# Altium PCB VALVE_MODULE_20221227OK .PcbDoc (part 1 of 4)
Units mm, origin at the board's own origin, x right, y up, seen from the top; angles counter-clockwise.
Board outline 260.15 x 142.01 mm, 2 copper layers (Top Layer, Bottom Layer); 455 components, 212 nets, 1302 pads, 385 vias.
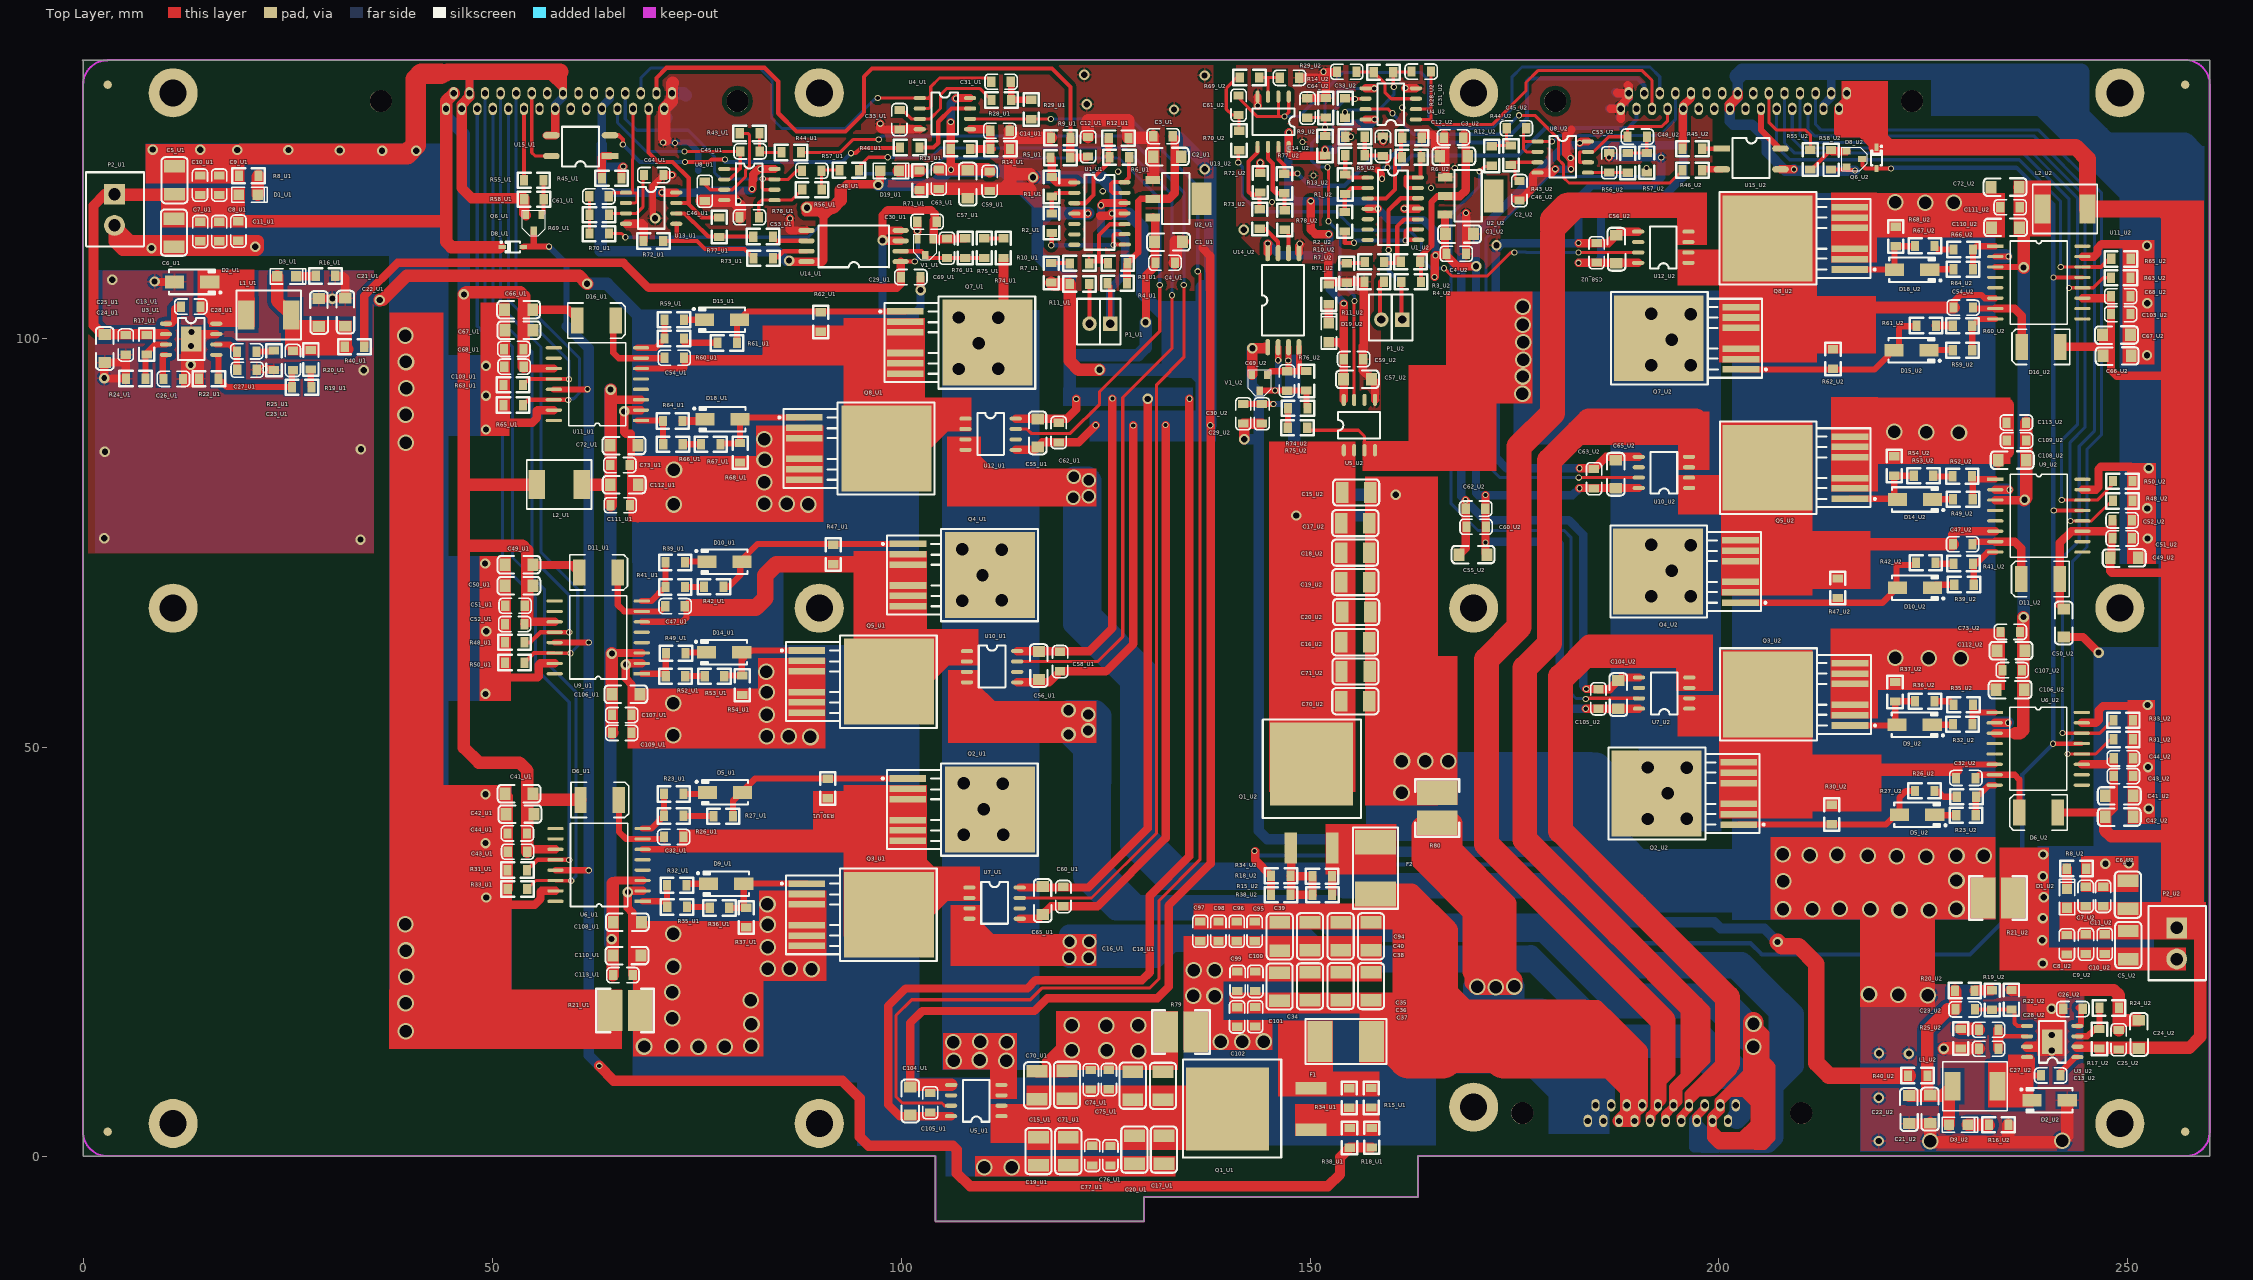
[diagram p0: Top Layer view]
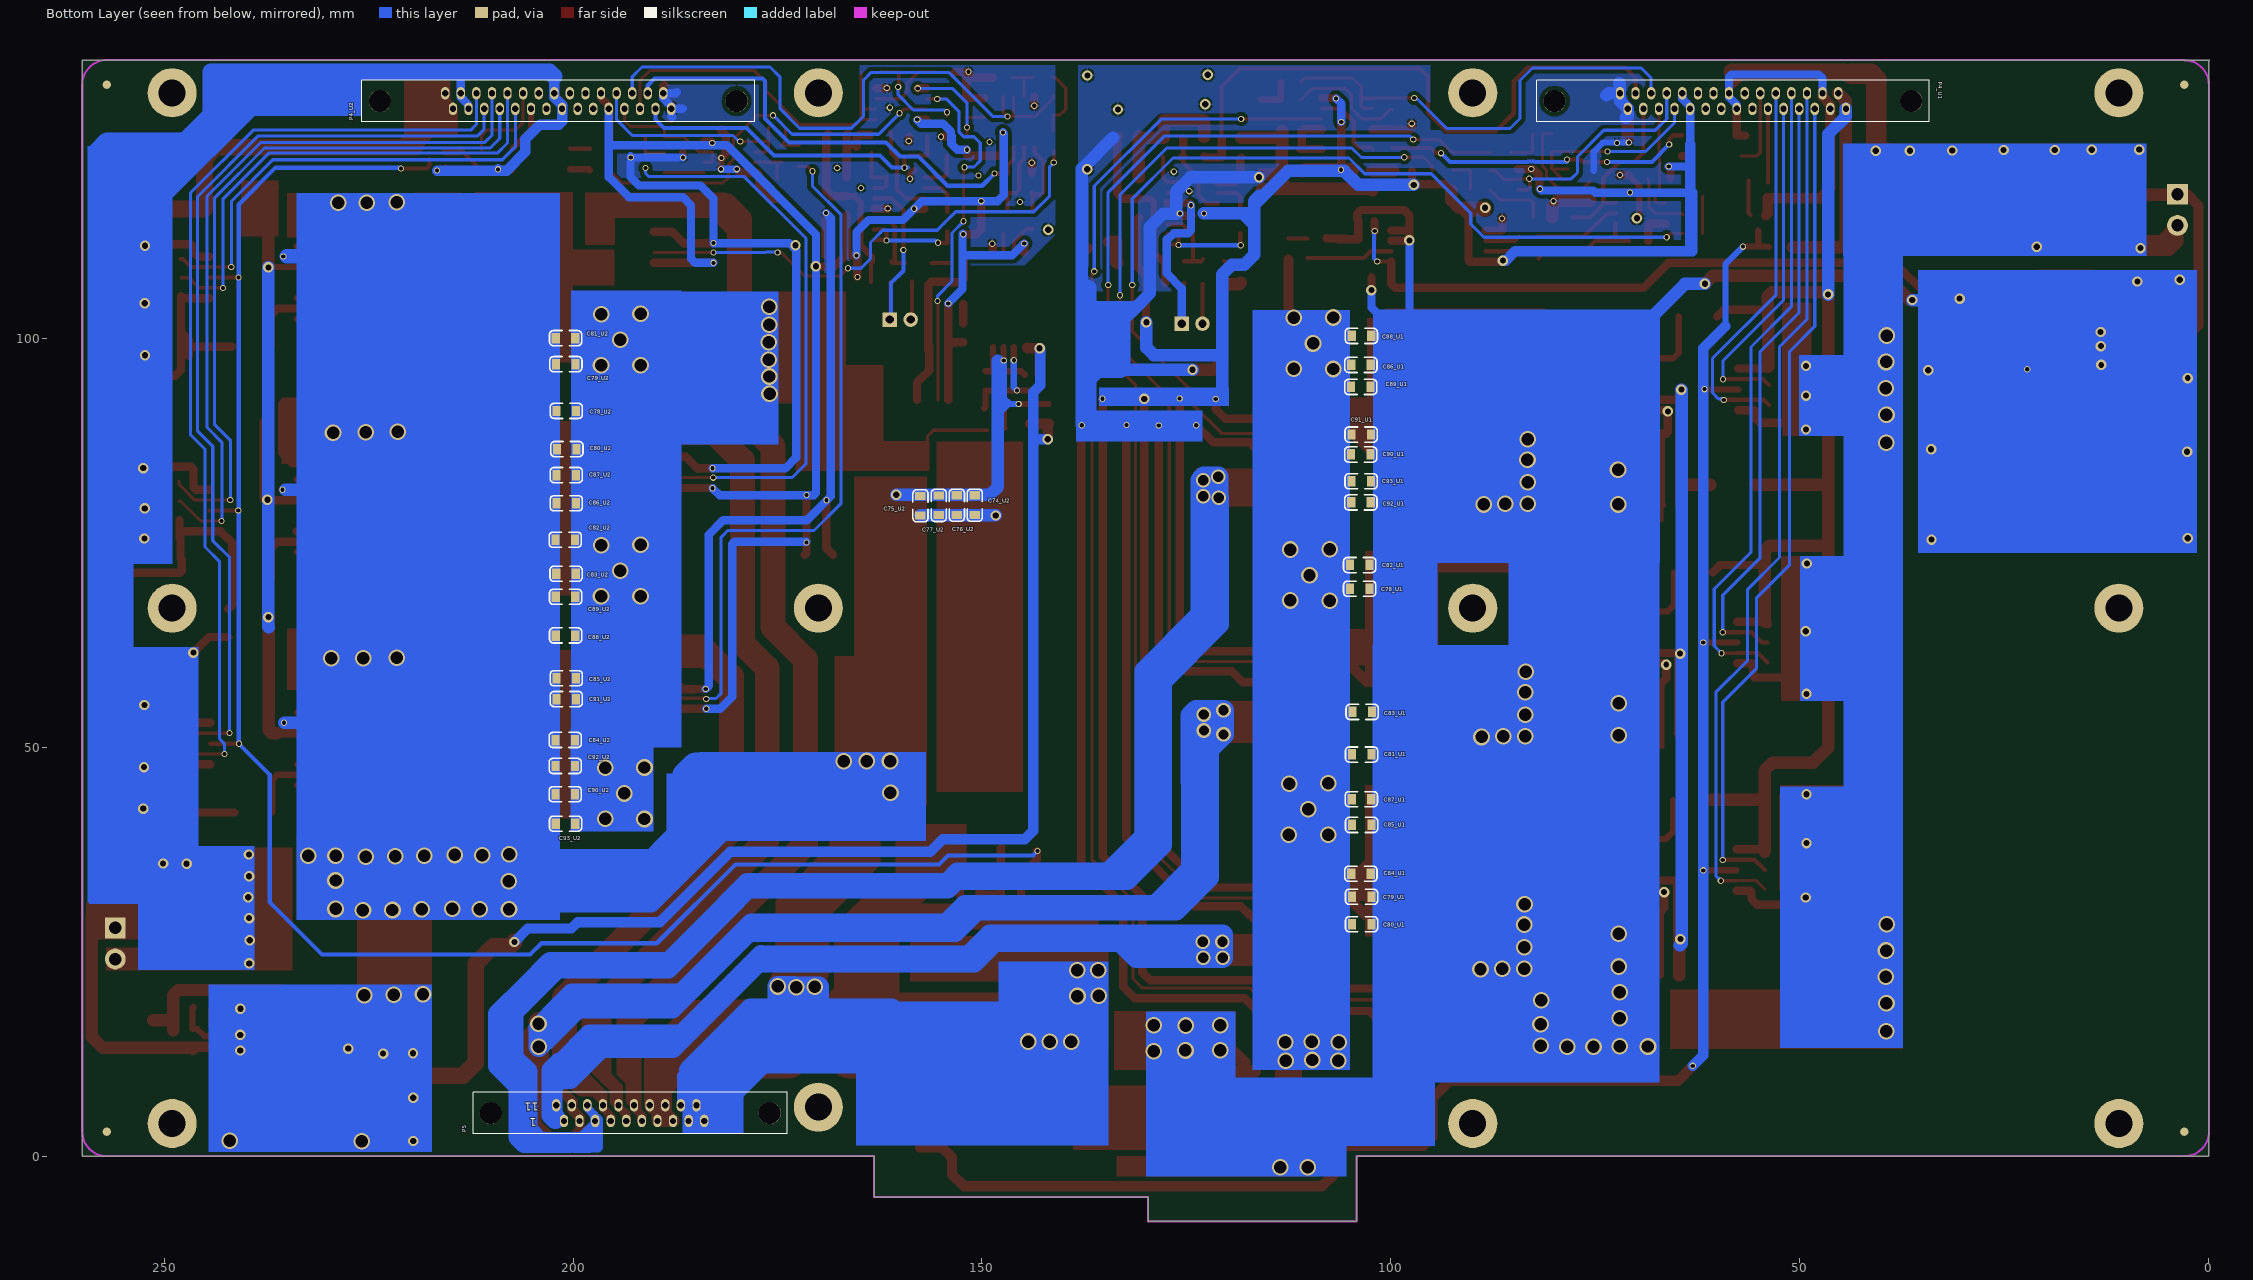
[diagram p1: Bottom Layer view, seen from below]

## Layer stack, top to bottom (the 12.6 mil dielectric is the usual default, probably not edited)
Top Layer: signal copper 0.0356
Dielectric: core 0.32, FR-4, Dk 4.8
Bottom Layer: signal copper 0.0356

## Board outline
-0.025,134.01 0,133.985 0,0 104.2,0 104.2,-7.925 129.624,-7.925 129.7,-8.001 129.7,-5 163.2,-5 163.2,0 260.02,0 260.02,134.01 -0.127,134.01

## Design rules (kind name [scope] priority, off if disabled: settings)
Clearance Clearance_1 [InPolygon] p1: gap=0.508
Clearance [All] p2: gap=0.254
HoleSize [All] p1: absolutevalues=TRUE maxlimit=12.7 minlimit=0.025 maxpercent=80.000 minpercent=20.000
MinimumSolderMaskSliver [All] p1: minsoldermaskwidth=0
PolygonConnect [All] p1: connectstyle=Relief reliefconductorwidth=0.254 reliefentries=4 polygonreliefangle="90 Angle" airgapwidth=0.254
RoutingVias [All] p1: holewidth=0.711 width=1.27 viastyle="Through Hole" minholewidth=0.508 minwidth=0.762 maxholewidth=2.032 maxwidth=2.54
SilkToSilkClearance [All] p1: silktosilkclearance=0
SilkToSolderMaskClearance [IsPad] p1: minsilkscreentomaskgap=0 clearancetoexposedcopper=TRUE
SolderMaskExpansion [All] p1: expansion=0.102
Width [All] p1: maxlimit=5.08 minlimit=0.254 preferedwidth=0.254 minimp=50.000000 maximp=50.000000 favimp=50.000000
24 further rules are at their usual default settings.

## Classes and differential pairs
channel class THREE_PHASE_MODULE: U1 U2
component class U3: C34 C35 C36 C37 C38 C39 C40 C94 C95 C96 C97 C98 C99 C100 C101 C102 F1 F2 P5 R79 R80
component class U2: C1_U2 C2_U2 C3_U2 C4_U2 C5_U2 C6_U2 C7_U2 C8_U2 C9_U2 C10_U2 C11_U2 C12_U2 C13_U2 C14_U2 C15_U2 C16_U2 C17_U2 C18_U2 C19_U2 C20_U2 C21_U2 C22_U2 C23_U2 C24_U2 C25_U2 C26_U2 C27_U2 C28_U2 C29_U2 C30_U2 C31_U2 C32_U2 C33_U2 C41_U2 C42_U2 C43_U2 C44_U2 C45_U2 C46_U2 C47_U2 C48_U2 C49_U2 C50_U2 C51_U2 C52_U2 C53_U2 C54_U2 C55_U2 C56_U2 C57_U2 C58_U2 C59_U2 C60_U2 C61_U2 C62_U2 C63_U2 C64_U2 C65_U2 C66_U2 C67_U2 C68_U2 C69_U2 C70_U2 C71_U2 C72_U2 C73_U2 C74_U2 C75_U2 C76_U2 C77_U2 C78_U2 C79_U2 C80_U2 C81_U2 C82_U2 C83_U2 C84_U2 C85_U2 C86_U2 C87_U2 C88_U2 C89_U2 C90_U2 C91_U2 C92_U2 C93_U2 C103_U2 C104_U2 C105_U2 C106_U2 C107_U2 C108_U2 C109_U2 C110_U2 C111_U2 C112_U2 C113_U2 D1_U2 D2_U2 D3_U2 D5_U2 D6_U2 D8_U2 D9_U2 D10_U2 D11_U2 D14_U2 D15_U2 D16_U2 D18_U2 D19_U2 L1_U2 L2_U2 P1_U2 P2_U2 P4_U2 Q1_U2 Q2_U2 Q3_U2 Q4_U2 Q5_U2 Q6_U2 Q7_U2 Q8_U2 R1_U2 R2_U2 R3_U2 R4_U2 R5_U2 R6_U2 R7_U2 R8_U2 R9_U2 R10_U2 R11_U2 R12_U2 R13_U2 R14_U2 R15_U2 R16_U2 R17_U2 R18_U2 R19_U2 R20_U2 R21_U2 R22_U2 R23_U2 R24_U2 R25_U2 R26_U2 R27_U2 R28_U2 R29_U2 R30_U2 R31_U2 R32_U2 R33_U2 R34_U2 R35_U2 R36_U2 R37_U2 R38_U2 R39_U2 R40_U2 R41_U2 R42_U2 R43_U2 R44_U2 R45_U2 R46_U2 R47_U2 R48_U2 R49_U2 R50_U2 R52_U2 R53_U2 R54_U2 R55_U2 R56_U2 R57_U2 R58_U2 R59_U2 R60_U2 R61_U2 R62_U2 R63_U2 R64_U2 R65_U2 R66_U2 R67_U2 R68_U2 R69_U2 R70_U2 R71_U2 R72_U2 R73_U2 R74_U2 R75_U2 R76_U2 R77_U2 R78_U2 U1_U2 U2_U2 U3_U2 U4_U2 U5_U2 U6_U2 U7_U2 U8_U2 U9_U2 U10_U2 U11_U2 U12_U2 U13_U2 U14_U2 U15_U2 V1_U2
component class U1: C1_U1 C2_U1 C3_U1 C4_U1 C5_U1 C6_U1 C7_U1 C8_U1 C9_U1 C10_U1 C11_U1 C12_U1 C13_U1 C14_U1 C15_U1 C16_U1 C17_U1 C18_U1 C19_U1 C20_U1 C21_U1 C22_U1 C23_U1 C24_U1 C25_U1 C26_U1 C27_U1 C28_U1 C29_U1 C30_U1 C31_U1 C32_U1 C33_U1 C41_U1 C42_U1 C43_U1 C44_U1 C45_U1 C46_U1 C47_U1 C48_U1 C49_U1 C50_U1 C51_U1 C52_U1 C53_U1 C54_U1 C55_U1 C56_U1 C57_U1 C58_U1 C59_U1 C60_U1 C61_U1 C62_U1 C63_U1 C64_U1 C65_U1 C66_U1 C67_U1 C68_U1 C69_U1 C70_U1 C71_U1 C72_U1 C73_U1 C74_U1 C75_U1 C76_U1 C77_U1 C78_U1 C79_U1 C80_U1 C81_U1 C82_U1 C83_U1 C84_U1 C85_U1 C86_U1 C87_U1 C88_U1 C89_U1 C90_U1 C91_U1 C92_U1 C93_U1 C103_U1 C104_U1 C105_U1 C106_U1 C107_U1 C108_U1 C109_U1 C110_U1 C111_U1 C112_U1 C113_U1 D1_U1 D2_U1 D3_U1 D5_U1 D6_U1 D8_U1 D9_U1 D10_U1 D11_U1 D14_U1 D15_U1 D16_U1 D18_U1 D19_U1 L1_U1 L2_U1 P1_U1 P2_U1 P4_U1 Q1_U1 Q2_U1 Q3_U1 Q4_U1 Q5_U1 Q6_U1 Q7_U1 Q8_U1 R1_U1 R2_U1 R3_U1 R4_U1 R5_U1 R6_U1 R7_U1 R8_U1 R9_U1 R10_U1 R11_U1 R12_U1 R13_U1 R14_U1 R15_U1 R16_U1 R17_U1 R18_U1 R19_U1 R20_U1 R21_U1 R22_U1 R23_U1 R24_U1 R25_U1 R26_U1 R27_U1 R28_U1 R29_U1 R30_U1 R31_U1 R32_U1 R33_U1 R34_U1 R35_U1 R36_U1 R37_U1 R38_U1 R39_U1 R40_U1 R41_U1 R42_U1 R43_U1 R44_U1 R45_U1 R46_U1 R47_U1 R48_U1 R49_U1 R50_U1 R52_U1 R53_U1 R54_U1 R55_U1 R56_U1 R57_U1 R58_U1 R59_U1 R60_U1 R61_U1 R62_U1 R63_U1 R64_U1 R65_U1 R66_U1 R67_U1 R68_U1 R69_U1 R70_U1 R71_U1 R72_U1 R73_U1 R74_U1 R75_U1 R76_U1 R77_U1 R78_U1 U1_U1 U2_U1 U3_U1 U4_U1 U5_U1 U6_U1 U7_U1 U8_U1 U9_U1 U10_U1 U11_U1 U12_U1 U13_U1 U14_U1 U15_U1 V1_U1

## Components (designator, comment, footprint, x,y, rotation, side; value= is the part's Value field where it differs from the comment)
C1_U1 "22uF/25V" WP_1206CC 130.988,111.785 r0 top (schematic designator C1)
C1_U2 "22uF/25V" WP_1206CC 166.573,112.751 r0 top (schematic designator C1)
C2_U1 "22uF/25V" WP_1206CC 134.264,122.199 r180 top (schematic designator C2)
C2_U2 "22uF/25V" WP_1206CC 169.291,122.225 r180 top (schematic designator C2)
C3_U1 "0.1uF/50V" WP_0805C 133.248,124.663 r180 top (schematic designator C3)
C3_U2 "0.1uF/50V" WP_0805C 168.758,124.511 r180 top (schematic designator C3)
C4_U1 "0.1uF/50V" WP_0805C 131.064,109.271 r0 top (schematic designator C4)
C4_U2 "0.1uF/50V" WP_0805C 166.675,110.363 r0 top (schematic designator C4)
C5_U1 "47uF/50V" WP_1210CC 11.176,117.602 r90 top (schematic designator C5)
C5_U2 "47uF/50V" WP_1210CC 250.038,27.534 r270 top (schematic designator C5)
C6_U1 "47uF/50V" WP_1210CC 11.1,114.63 r270 top (schematic designator C6)
C6_U2 "47uF/50V" WP_1210CC 249.987,30.251 r90 top (schematic designator C6)
C7_U1 "0.1uF/50V" WP_0805C 14.275,111.836 r90 top (schematic designator C7)
C7_U2 "0.1uF/50V" WP_0805C 244.856,32.969 r270 top (schematic designator C7)
C8_U1 "0.1uF/50V" WP_0805C 16.612,111.836 r90 top (schematic designator C8)
C8_U2 "0.1uF/50V" WP_0805C 242.494,24.638 r90 top (schematic designator C8)
C9_U1 "0.1uF/50V" WP_0805C 16.688,119.939 r270 top (schematic designator C9)
C9_U2 "0.1uF/50V" WP_0805C 244.831,24.714 r90 top (schematic designator C9)
C10_U1 "0.1uF/50V" WP_0805C 14.326,119.939 r270 top (schematic designator C10)
C10_U2 "0.1uF/50V" WP_0805C 247.117,24.714 r90 top (schematic designator C10)
C11_U1 "0.1uF/50V" WP_0805C 18.948,111.887 r90 top (schematic designator C11)
C11_U2 "0.1uF/50V" WP_0805C 246.99,32.969 r270 top (schematic designator C11)
C12_U1 "0.1uF/50V" WP_0805C 122.834,122.199 r90 top (schematic designator C12)
C12_U2 "0.1uF/50V" WP_0805C 158.877,122.25 r90 top (schematic designator C12)
C13_U1 "0.1uF/50V" WP_0805C 14.376,103.835 r180 top (schematic designator C13)
C13_U2 "0.1uF/50V" WP_0805C 239.344,9.906 r0 top (schematic designator C13)
C14_U1 "0.1uF/50V" WP_0805C 110.871,125.4 r0 top (schematic designator C14)
C14_U2 "0.1uF/50V" WP_0805C 149.657,126.924 r90 top (schematic designator C14)
C15_U1 "47uF/100V" WP_1210CC 120.294,7.01 r90 top (schematic designator C15)
C15_U2 "47uF/100V" WP_1210CC 153.924,81.153 r0 top (schematic designator C15)
C16_U1 "47uF/100V" WP_1210CC 128.321,6.909 r90 top (schematic designator C16)
C16_U2 "47uF/100V" WP_1210CC 153.797,62.84 r0 top (schematic designator C16)
C17_U1 "47uF/100V" WP_1210CC 132.131,2.515 r270 top (schematic designator C17)
C17_U2 "47uF/100V" WP_1210CC 153.822,77.394 r0 top (schematic designator C17)
C18_U1 "47uF/100V" WP_1210CC 132.029,6.883 r90 top (schematic designator C18)
C18_U2 "47uF/100V" WP_1210CC 153.797,73.787 r0 top (schematic designator C18)
C19_U1 "47uF/100V" WP_1210CC 116.789,2.337 r270 top (schematic designator C19)
C19_U2 "47uF/100V" WP_1210CC 153.822,70.18 r0 top (schematic designator C19)
C20_U1 "47uF/100V" WP_1210CC 128.524,2.515 r270 top (schematic designator C20)
C20_U2 "47uF/100V" WP_1210CC 153.924,66.523 r0 top (schematic designator C20)
C21_U1 "22uF/25V" WP_1206CC 28.829,101.422 r90 top (schematic designator C21)
C21_U2 "22uF/25V" WP_1206CC 225.806,7.468 r270 top (schematic designator C21)
C22_U1 "22uF/25V" WP_1206CC 32.055,101.473 r90 top (schematic designator C22)
C22_U2 "22uF/25V" WP_1206CC 223.241,7.417 r270 top (schematic designator C22)
C23_U1 "100pF/50V" WP_0805C 25.679,98.501 r270 top (schematic designator C23)
C23_U2 "100pF/50V" WP_0805C 228.879,17.983 r0 top (schematic designator C23)
C24_U1 "22uF/25V" WP_1206CC 2.667,100.457 r270 top (schematic designator C24)
C24_U2 "22uF/25V" WP_1206CC 251.333,13.183 r90 top (schematic designator C24)
C25_U1 "0.1uF/50V" WP_0805C 5.182,97.968 r90 top (schematic designator C25)
C25_U2 "0.1uF/50V" WP_0805C 248.895,15.443 r270 top (schematic designator C25)
C26_U1 "0.01uF/50V" WP_0805C 12.243,94.996 r180 top (schematic designator C26)
C26_U2 "0.01uF/50V" WP_0805C 242.062,18.034 r0 top (schematic designator C26)
C27_U1 "22pF/50V" WP_0805C 21.26,96.114 r180 top (schematic designator C27)
C27_U2 "22pF/50V" WP_0805C 231.75,13.183 r0 top (schematic designator C27)
C28_U1 "2.2nF/50V" WP_0805C 21.209,98.349 r180 top (schematic designator C28)
C28_U2 "2.2nF/50V" WP_0805C 231.75,15.494 r0 top (schematic designator C28)
C29_U1 "0.1uF/50V" WP_0805C 102.413,107.442 r180 top (schematic designator C29)
C29_U2 "0.1uF/50V" WP_0805C 144.145,91.973 r270 top (schematic designator C29)
C30_U1 "0.1uF/50V" WP_0805C 104.394,114.198 r180 top (schematic designator C30)
C30_U2 "0.1uF/50V" WP_0805C 141.884,91.973 r270 top (schematic designator C30)
C31_U1 "10nF/50V" WP_0805C 113.436,131.318 r180 top (schematic designator C31)
C31_U2 "10nF/50V" WP_0805C 162.382,132.639 r0 top (schematic designator C31)
C32_U1 "1uF/50V" WP_0805C 70.993,39.065 r0 top (schematic designator C32)
C32_U2 "1uF/50V" WP_0805C 231.394,46.203 r180 top (schematic designator C32)
C33_U1 "3.3nF/50V" WP_0805C 99.847,127.94 r270 top (schematic designator C33)
C33_U2 "3.3nF/50V" WP_0805C 155.702,132.537 r180 top (schematic designator C33)
C34 "47uF/100V" WP_1210CC 146.279,19.025 r90 top
C35 "47uF/100V" WP_1210CC 149.987,19.05 r90 top
C36 "47uF/100V" WP_1210CC 157.455,19.075 r90 top
C37 "47uF/100V" WP_1210CC 153.746,19.075 r90 top
C38 "47uF/100V" WP_1210CC 149.987,28.6 r270 top
C39 "47uF/100V" WP_1210CC 146.304,28.575 r270 top
C40 "47uF/100V" WP_1210CC 153.746,28.6 r270 top
C41_U1 "10uF/50V" WP_1206CC 55.016,44.298 r180 top (schematic designator C41)
C41_U2 "10uF/50V" WP_1206CC 247.218,44.069 r0 top (schematic designator C41)
C42_U1 "10uF/50V" WP_1206CC 55.118,41.808 r180 top (schematic designator C42)
C42_U2 "10uF/50V" WP_1206CC 247.218,41.478 r0 top (schematic designator C42)
C43_U1 "0.1uF/50V" WP_0805C 54.331,37.186 r180 top (schematic designator C43)
C43_U2 "0.1uF/50V" WP_0805C 248.234,46.507 r0 top (schematic designator C43)
C44_U1 "0.1uF/50V" WP_0805C 54.305,39.421 r180 top (schematic designator C44)
C44_U2 "0.1uF/50V" WP_0805C 248.234,48.666 r0 top (schematic designator C44)
C45_U1 "10nF/50V" WP_0805C 82.753,122.809 r180 top (schematic designator C45)
C45_U2 "10nF/50V" WP_0805C 174.015,125.705 r0 top (schematic designator C45)
C46_U1 "3.3nF/50V" WP_0805C 76.048,119.177 r270 top (schematic designator C46)
C46_U2 "3.3nF/50V" WP_0805C 175.641,119.253 r270 top (schematic designator C46)
C47_U1 "Cap Semi" WP_0805C 73.584,67.208 r180 top (schematic designator C47)
C47_U2 "Cap Semi" WP_0805C 228.575,74.854 r0 top (schematic designator C47)
C48_U1 "10nF/50V" WP_0805C 90.297,120.447 r180 top (schematic designator C48)
C48_U2 "10nF/50V" WP_0805C 191.237,124.612 r180 top (schematic designator C48)
C49_U1 "10uF/50V" WP_1206CC 54.991,72.288 r180 top (schematic designator C49)
C49_U2 "10uF/50V" WP_1206CC 247.828,73.152 r0 top (schematic designator C49)
C50_U1 "10uF/50V" WP_1206CC 54.991,69.723 r180 top (schematic designator C50)
C50_U2 "10uF/50V" WP_1206CC 242.164,66.904 r270 top (schematic designator C50)
C51_U1 "0.1uF/50V" WP_0805C 54.026,67.259 r180 top (schematic designator C51)
C51_U2 "0.1uF/50V" WP_0805C 248.082,75.565 r0 top (schematic designator C51)
C52_U1 "0.1uF/50V" WP_0805C 53.975,65.024 r180 top (schematic designator C52)
C52_U2 "0.1uF/50V" WP_0805C 248.082,77.775 r0 top (schematic designator C52)
C53_U1 "3.3nF/50V" WP_0805C 82.677,114.757 r180 top (schematic designator C53)
C53_U2 "3.3nF/50V" WP_0805C 186.538,120.244 r90 top (schematic designator C53)
C54_U1 "Cap Semi" WP_0805C 73.482,97.587 r180 top (schematic designator C54)
C54_U2 "Cap Semi" WP_0805C 228.651,103.784 r0 top (schematic designator C54)
C55_U1 "22uF/25V" WP_1206CC 116.713,90.145 r270 top (schematic designator C55)
C55_U2 "22uF/25V" WP_1206CC 171.653,73.533 r180 top (schematic designator C55)
C56_U1 "22uF/25V" WP_1206CC 116.865,61.697 r270 top (schematic designator C56)
C56_U2 "22uF/25V" WP_1206CC 187.452,109.169 r90 top (schematic designator C56)
C57_U1 "22uF/25V" WP_1206CC 108.179,120.548 r270 top (schematic designator C57)
C57_U2 "22uF/25V" WP_1206CC 154.076,94.996 r0 top (schematic designator C57)
C58_U1 "0.1uF/50V" WP_0805C 119.405,59.258 r90 top (schematic designator C58)
C58_U2 "0.1uF/50V" WP_0805C 185.064,111.658 r270 top (schematic designator C58)
C59_U1 "0.1uF/50V" WP_0805C 110.795,117.983 r90 top (schematic designator C59)
C59_U2 "0.1uF/50V" WP_0805C 156.54,97.409 r180 top (schematic designator C59)
C60_U1 "0.1uF/50V" WP_0805C 119.812,30.531 r90 top (schematic designator C60)
C60_U2 "0.1uF/50V" WP_0805C 169.088,76.987 r0 top (schematic designator C60)
C61_U1 "10nF/50V" WP_0805C 61.849,117.373 r0 top (schematic designator C61)
C61_U2 "10nF/50V" WP_0805C 141.224,127.279 r90 top (schematic designator C61)
C62_U1 "1uF/50V" WP_0805C 119.304,89.687 r270 top (schematic designator C62)
C62_U2 "1uF/50V" WP_0805C 171.45,79.146 r180 top (schematic designator C62)
C63_U1 "0.1uF/50V" WP_0805C 104.648,120.675 r270 top (schematic designator C63)
C63_U2 "0.1uF/50V" WP_0805C 184.683,81.61 r90 top (schematic designator C63)
C64_U1 "3.3nF/50V" WP_0805C 68.555,119.99 r0 top (schematic designator C64)
C64_U2 "3.3nF/50V" WP_0805C 146.279,131.877 r0 top (schematic designator C64)
C65_U1 "22uF/25V" WP_1206CC 117.323,32.969 r270 top (schematic designator C65)
C65_U2 "22uF/25V" WP_1206CC 187.35,81.661 r90 top (schematic designator C65)
C66_U1 "10uF/50V" WP_1206CC 54.966,103.48 r180 top (schematic designator C66)
C66_U2 "10uF/50V" WP_1206CC 246.964,97.841 r0 top (schematic designator C66)
C67_U1 "10uF/50V" WP_1206CC 54.991,100.965 r180 top (schematic designator C67)
C67_U2 "10uF/50V" WP_1206CC 246.888,100.406 r0 top (schematic designator C67)
C68_U1 "0.1uF/50V" WP_0805C 53.873,98.654 r180 top (schematic designator C68)
C68_U2 "0.1uF/50V" WP_0805C 247.904,105.181 r0 top (schematic designator C68)
C69_U1 "1nF/50V" WP_0805C 105.639,112.217 r270 top (schematic designator C69)
C69_U2 "1nF/50V" WP_0805C 147.218,95.987 r270 top (schematic designator C69)
C70_U1 "47uF/100V" WP_1210CC 116.637,6.96 r90 top (schematic designator C70)
C70_U2 "47uF/100V" WP_1210CC 153.822,55.626 r0 top (schematic designator C70)
C71_U1 "47uF/100V" WP_1210CC 120.447,2.337 r270 top (schematic designator C71)
C71_U2 "47uF/100V" WP_1210CC 153.848,59.258 r0 top (schematic designator C71)
C72_U1 "10uF/50V" WP_1206CC 64.414,86.893 r0 top (schematic designator C72)
C72_U2 "10uF/50V" WP_1206CC 236.703,118.466 r180 top (schematic designator C72)
C73_U1 "0.1uF/50V" WP_0805C 64.414,84.531 r0 top (schematic designator C73)
C73_U2 "0.1uF/50V" WP_0805C 236.83,64.059 r180 top (schematic designator C73)
C74_U1 "0.1uF/50V" WP_0805C 123.165,8.128 r90 top (schematic designator C74)
C74_U2 "0.1uF/50V" WP_0805C 150.927,78.384 r90 bottom (schematic designator C74)
C75_U1 "0.1uF/50V" WP_0805C 125.374,8.153 r90 top (schematic designator C75)
C75_U2 "0.1uF/50V" WP_0805C 157.556,78.308 r90 bottom (schematic designator C75)
C76_U1 "0.1uF/50V" WP_0805C 125.628,1.27 r270 top (schematic designator C76)
C76_U2 "0.1uF/50V" WP_0805C 153.111,78.384 r90 bottom (schematic designator C76)
C77_U1 "0.1uF/50V" WP_0805C 123.419,1.295 r270 top (schematic designator C77)
C77_U2 "0.1uF/50V" WP_0805C 155.321,78.359 r90 bottom (schematic designator C77)
C78_U1 "0.1uF/50V" WP_0805C 105.029,69.418 r180 bottom (schematic designator C78)
C78_U2 "0.1uF/50V" WP_0805C 199.619,91.084 r0 bottom (schematic designator C78)
C79_U1 "0.1uF/50V" WP_0805C 104.8,31.75 r180 bottom (schematic designator C79)
C79_U2 "0.1uF/50V" WP_0805C 199.669,96.799 r0 bottom (schematic designator C79)
C80_U1 "0.1uF/50V" WP_0805C 104.8,28.397 r180 bottom (schematic designator C80)
C80_U2 "0.1uF/50V" WP_0805C 199.542,86.411 r0 bottom (schematic designator C80)
C81_U1 "0.1uF/50V" WP_0805C 104.8,49.149 r180 bottom (schematic designator C81)
C81_U2 "0.1uF/50V" WP_0805C 199.695,99.974 r0 bottom (schematic designator C81)
C82_U1 "0.1uF/50V" WP_0805C 105.029,72.314 r180 bottom (schematic designator C82)
C82_U2 "0.1uF/50V" WP_0805C 199.746,75.336 r0 bottom (schematic designator C82)
C83_U1 "0.1uF/50V" WP_0805C 104.724,54.356 r180 bottom (schematic designator C83)
C83_U2 "0.1uF/50V" WP_0805C 199.644,71.171 r0 bottom (schematic designator C83)
C84_U1 "0.1uF/50V" WP_0805C 104.877,34.569 r180 bottom (schematic designator C84)
C84_U2 "0.1uF/50V" WP_0805C 199.746,50.851 r0 bottom (schematic designator C84)
C85_U1 "0.1uF/50V" WP_0805C 104.8,40.538 r180 bottom (schematic designator C85)
C85_U2 "0.1uF/50V" WP_0805C 199.619,58.395 r0 bottom (schematic designator C85)
C86_U1 "0.1uF/50V" WP_0805C 104.877,96.774 r180 bottom (schematic designator C86)
C86_U2 "0.1uF/50V" WP_0805C 199.619,79.781 r0 bottom (schematic designator C86)
C87_U1 "0.1uF/50V" WP_0805C 104.826,43.688 r180 bottom (schematic designator C87)
C87_U2 "0.1uF/50V" WP_0805C 199.619,83.236 r0 bottom (schematic designator C87)
C88_U1 "0.1uF/50V" WP_0805C 104.826,100.33 r180 bottom (schematic designator C88)
C88_U2 "0.1uF/50V" WP_0805C 199.695,63.627 r0 bottom (schematic designator C88)
C89_U1 "0.1uF/50V" WP_0805C 104.902,94.082 r180 bottom (schematic designator C89)
C89_U2 "0.1uF/50V" WP_0805C 199.695,68.351 r0 bottom (schematic designator C89)
C90_U1 "0.1uF/50V" WP_0805C 104.902,85.827 r180 bottom (schematic designator C90)
C90_U2 "0.1uF/50V" WP_0805C 199.746,44.221 r0 bottom (schematic designator C90)
C91_U1 "0.1uF/50V" WP_0805C 104.851,88.265 r180 bottom (schematic designator C91)
C91_U2 "0.1uF/50V" WP_0805C 199.619,55.855 r0 bottom (schematic designator C91)
C92_U1 "0.1uF/50V" WP_0805C 104.877,79.959 r180 bottom (schematic designator C92)
C92_U2 "0.1uF/50V" WP_0805C 199.746,47.676 r0 bottom (schematic designator C92)
C93_U1 "0.1uF/50V" WP_0805C 104.851,82.55 r180 bottom (schematic designator C93)
C93_U2 "0.1uF/50V" WP_0805C 199.695,40.615 r0 bottom (schematic designator C93)
C94 "47uF/100V" WP_1210CC 157.455,28.6 r270 top
C95 "0.1uF/50V" WP_0805C 143.256,28.702 r270 top
C96 "0.1uF/50V" WP_0805C 141.072,28.702 r270 top
C97 "0.1uF/50V" WP_0805C 136.627,28.702 r270 top
C98 "0.1uF/50V" WP_0805C 138.836,28.702 r270 top
C99 "0.1uF/50V" WP_0805C 141.097,20.168 r90 top
C100 "0.1uF/50V" WP_0805C 143.281,20.168 r90 top
C101 "0.1uF/50V" WP_0805C 143.332,18.263 r270 top
C102 "0.1uF/50V" WP_0805C 141.122,18.237 r270 top
C103_U1 "0.1uF/50V" WP_0805C 53.899,96.495 r180 top (schematic designator C103)
C103_U2 "0.1uF/50V" WP_0805C 247.904,102.997 r0 top (schematic designator C103)
C104_U1 "22uF/25V" WP_1206CC 101.117,5.029 r90 top (schematic designator C104)
C104_U2 "22uF/25V" WP_1206CC 187.681,54.712 r90 top (schematic designator C104)
C105_U1 "0.1uF/50V" WP_0805C 103.607,7.747 r270 top (schematic designator C105)
C105_U2 "0.1uF/50V" WP_0805C 185.293,57.125 r270 top (schematic designator C105)
C106_U1 "10uF/50V" WP_1206CC 64.643,56.49 r0 top (schematic designator C106)
C106_U2 "10uF/50V" WP_1206CC 237.312,57.023 r180 top (schematic designator C106)
C107_U1 "0.1uF/50V" WP_0805C 64.643,53.975 r0 top (schematic designator C107)
C107_U2 "0.1uF/50V" WP_0805C 237.058,59.385 r180 top (schematic designator C107)
C108_U1 "10uF/50V" WP_1206CC 64.821,28.626 r0 top (schematic designator C108)
C108_U2 "10uF/50V" WP_1206CC 237.566,85.09 r180 top (schematic designator C108)
C109_U1 "0.1uF/50V" WP_0805C 64.643,51.791 r0 top (schematic designator C109)
C109_U2 "0.1uF/50V" WP_0805C 237.592,87.478 r180 top (schematic designator C109)
C110_U1 "10uF/50V" WP_1206CC 64.77,24.536 r0 top (schematic designator C110)
C110_U2 "10uF/50V" WP_1206CC 236.753,113.538 r180 top (schematic designator C110)
C111_U1 "0.1uF/50V" WP_0805C 64.465,79.629 r0 top (schematic designator C111)
C111_U2 "0.1uF/50V" WP_0805C 236.804,115.976 r180 top (schematic designator C111)
C112_U1 "10uF/50V" WP_1206CC 64.44,82.118 r0 top (schematic designator C112)
C112_U2 "10uF/50V" WP_1206CC 237.414,61.798 r180 top (schematic designator C112)
C113_U1 "0.1uF/50V" WP_0805C 64.795,22.174 r0 top (schematic designator C113)
C113_U2 "0.1uF/50V" WP_0805C 237.566,89.662 r180 top (schematic designator C113)
D1_U1 "" WP_0805_LED 19.025,117.551 r0 top (schematic designator D1)
D1_U2 "" WP_0805_LED 242.545,30.353 r90 top (schematic designator D1)
D2_U1 "1N5822" WP_SMA_DO214AC 11.176,106.883 r0 top (schematic designator D2)
D2_U2 "1N5822" WP_SMA_DO214AC 242.57,6.858 r180 top (schematic designator D2)
D3_U1 "LED" WP_0805_LED 23.724,107.569 r0 top (schematic designator D3)
D3_U2 "LED" WP_0805_LED 228.117,3.861 r0 top (schematic designator D3)
D5_U1 "1N5822" WP_SMA_DO214AC 80.62,44.475 r180 top (schematic designator D5)
D5_U2 "1N5822" WP_SMA_DO214AC 222.072,41.758 r0 top (schematic designator D5)
D6_U1 "STTH112U" WP_1812D 60.808,43.561 r0 top (schematic designator D6)
D6_U2 "STTH112U" WP_1812D 241.427,42.012 r180 top (schematic designator D6)
D8_U1 "1N5819" WP_SOD-323 53.797,111.176 r180 top (schematic designator D8)
D8_U2 "1N5819" WP_SOD-323 219.304,120.777 r90 top (schematic designator D8)
D9_U1 "1N5822" WP_SMA_DO214AC 80.772,33.299 r180 top (schematic designator D9)
D9_U2 "1N5822" WP_SMA_DO214AC 221.767,52.756 r0 top (schematic designator D9)
D10_U1 "1N5822" WP_SMA_DO214AC 80.569,72.695 r180 top (schematic designator D10)
D10_U2 "1N5822" WP_SMA_DO214AC 221.818,69.494 r0 top (schematic designator D10)
D11_U1 "STTH112U" WP_1812D 60.655,71.374 r0 top (schematic designator D11)
D11_U2 "STTH112U" WP_1812D 241.656,70.561 r180 top (schematic designator D11)
D14_U1 "1N5822" WP_SMA_DO214AC 80.518,61.595 r180 top (schematic designator D14)
D14_U2 "1N5822" WP_SMA_DO214AC 221.818,80.289 r0 top (schematic designator D14)
D15_U1 "1N5822" WP_SMA_DO214AC 80.264,102.26 r180 top (schematic designator D15)
D15_U2 "1N5822" WP_SMA_DO214AC 221.386,98.552 r0 top (schematic designator D15)
D16_U1 "STTH112U" WP_1812D 60.401,102.159 r0 top (schematic designator D16)
D16_U2 "STTH112U" WP_1812D 241.706,98.958 r180 top (schematic designator D16)
D18_U1 "1N5822" WP_SMA_DO214AC 80.315,90.094 r180 top (schematic designator D18)
D18_U2 "1N5822" WP_SMA_DO214AC 221.463,108.382 r0 top (schematic designator D18)
D19_U1 "LED" WP_0805_LED 97.434,120.472 r0 top (schematic designator D19)
D19_U2 "LED" WP_0805_LED 152.298,99.517 r90 top (schematic designator D19)
F1 "SMD2920R700SF" WP_2420 157.531,14.021 r180 top
F2 "SMD2920R700SF" WP_2420 157.988,32.08 r90 top
L1_U1 "10uH/2A" WP_LBS6*6 25.451,102.845 r180 top (schematic designator L1)
L1_U2 "10uH/2A" WP_LBS6*6 228.549,8.56 r0 top (schematic designator L1)
L2_U1 "10uH/2A" WP_LBS6*6 60.96,82.118 r180 top (schematic designator L2)
L2_U2 "10uH/2A" WP_LBS6*6 239.547,115.799 r0 top (schematic designator L2)
P1_U1 "Header 2" WP_SIP2 125.578,101.778 r180 top (schematic designator P1)
P1_U2 "Header 2" WP_SIP2 161.265,102.286 r180 top (schematic designator P1)
P2_U1 "Header 2" WP_LSIP2 3.835,117.602 r270 top (schematic designator P2)
P2_U2 "Header 2" WP_LSIP2 255.956,27.915 r270 top (schematic designator P2)
P4_U1 "Header 15X2A" WP_CRM222-030 44.374,128.047 r180 bottom locked (schematic designator P4)
P4_U2 "Header 15X2A" WP_CRM222-030 215.623,129.952 r0 bottom locked (schematic designator P4)
P5 "Header 10X2A" WP_CRM222-020 202.057,6.223 r0 bottom
Q1_U1 "IPB110P06LM" WP_TO263-3 150.139,3.226 r90 top (schematic designator Q7)
Q1_U2 "IPB110P06LM" WP_TO263-3 147.625,37.694 r0 top (schematic designator Q7)
Q2_U1 "IPB017N10N5L" JY_TO263-7 100.813,46.177 r270 top (schematic designator Q7)
Q2_U2 "IPB017N10N5L" JY_TO263-7 202.413,40.538 r90 top (schematic designator Q7)
Q3_U1 "IPB017N10N5L" JY_TO263-7 88.468,33.325 r270 top (schematic designator Q7)
Q3_U2 "IPB017N10N5L" JY_TO263-7 216.027,52.654 r90 top (schematic designator Q7)
Q4_U1 "IPB017N10N5L" JY_TO263-7 100.838,74.854 r270 top (schematic designator Q7)
Q4_U2 "IPB017N10N5L" JY_TO263-7 202.616,67.666 r90 top (schematic designator Q7)
Q5_U1 "IPB017N10N5L" JY_TO263-7 88.468,61.824 r270 top (schematic designator Q7)
Q5_U2 "IPB017N10N5L" JY_TO263-7 216.002,80.366 r90 top (schematic designator Q7)
Q6_U1 "MMBT4401" WP_SOT23B 56.032,115.062 r180 top (schematic designator Q6)
Q6_U2 "MMBT4401" WP_SOT23B 215.595,122.86 r270 top (schematic designator Q6)
Q7_U1 "IPB017N10N5L" JY_TO263-7 100.508,103.276 r270 top (schematic designator Q7)
Q7_U2 "IPB017N10N5L" JY_TO263-7 202.692,96.19 r90 top (schematic designator Q7)
Q8_U1 "IPB017N10N5L" JY_TO263-7 88.163,90.322 r270 top (schematic designator Q7)
Q8_U2 "IPB017N10N5L" JY_TO263-7 215.976,108.407 r90 top (schematic designator Q7)
R1_U1 "10K/0.1%" WP_0805R 118.415,119.71 r270 top (schematic designator R1)
R1_U2 "10K/0.1%" WP_0805R 154.305,120.015 r270 top (schematic designator R1)
R2_U1 "1K/0.1%" WP_0805R 118.415,115.265 r270 top (schematic designator R2)
R2_U2 "1K/0.1%" WP_0805R 154.254,115.443 r270 top (schematic designator R2)
R3_U1 "3K/0.1%" WP_0805R 127.686,109.169 r180 top (schematic designator R3)
R3_U2 "3K/0.1%" WP_0805R 163.474,109.347 r180 top (schematic designator R3)
R4_U1 "3K/0.1%" WP_0805R 127.635,106.731 r180 top (schematic designator R4)
R4_U2 "3K/0.1%" WP_0805R 163.551,106.883 r180 top (schematic designator R4)
R5_U1 "1K/0.1%" WP_0805R 118.288,122.098 r0 top (schematic designator R5)
R5_U2 "1K/0.1%" WP_0805R 154.305,122.352 r0 top (schematic designator R5)
R6_U1 "1K/0.1%" WP_0805R 125.501,122.123 r0 top (schematic designator R6)
R6_U2 "1K/0.1%" WP_0805R 161.239,122.149 r0 top (schematic designator R6)
R7_U1 "620R/0.1%" WP_0805R 123.012,109.144 r180 top (schematic designator R7)
R7_U2 "620R/0.1%" WP_0805R 159.08,109.322 r180 top (schematic designator R7)
R8_U1 "10K" WP_0805R 19.05,119.863 r0 top (schematic designator R8)
R8_U2 "10K" WP_0805R 244.907,35.154 r180 top (schematic designator R8)
R9_U1 "2K/0.1%" WP_0805R 118.313,124.511 r0 top (schematic designator R9)
R9_U2 "2K/0.1%" WP_0805R 154.305,124.638 r0 top (schematic designator R9)
R10_U1 "100R/0.1%" WP_0805R 118.364,106.807 r90 top (schematic designator R10)
R10_U2 "100R/0.1%" WP_0805R 154.483,106.782 r90 top (schematic designator R10)
R11_U1 "0R" WP_0805R 123.012,106.629 r180 top (schematic designator R11)
R11_U2 "0R" WP_0805R 159.029,106.909 r180 top (schematic designator R11)
R12_U1 "10K/0.1%" WP_0805R 125.4,124.485 r0 top (schematic designator R12)
R12_U2 "10K/0.1%" WP_0805R 161.265,124.536 r0 top (schematic designator R12)
R13_U1 "2K" WP_0805R 108.458,123.139 r180 top (schematic designator R13)
R13_U2 "2K" WP_0805R 151.841,124.714 r270 top (schematic designator R13)
R14_U1 "10K" WP_0805R 113.335,123.139 r180 top (schematic designator R14)
R14_U2 "10K" WP_0805R 151.917,129.362 r270 top (schematic designator R14)
R15_U1 "10K" WP_0805R 157.48,8.331 r270 top (schematic designator R15)
R15_U2 "10K" WP_0805R 152.705,31.953 r180 top (schematic designator R15)
R16_U1 "3K" WP_0805R 28.448,107.62 r0 top (schematic designator R16)
R16_U2 "3K" WP_0805R 232.994,3.861 r0 top (schematic designator R16)
R17_U1 "30K" WP_0805R 7.772,100.406 r270 top (schematic designator R17)
R17_U2 "30K" WP_0805R 246.507,13.157 r90 top (schematic designator R17)
R18_U1 "20K" WP_0805R 157.556,3.454 r270 top (schematic designator R18)
R18_U2 "20K" WP_0805R 147.625,34.265 r180 top (schematic designator R18)
R19_U1 "51K" WP_0805R 25.552,94.031 r0 top (schematic designator R19)
R19_U2 "51K" WP_0805R 233.375,17.907 r90 top (schematic designator R19)
R20_U1 "2K" WP_0805R 27.838,96.19 r90 top (schematic designator R20)
R20_U2 "2K" WP_0805R 231.242,20.244 r180 top (schematic designator R20)
R21_U1 "0R" WP_JS2L 64.516,17.831 r0 top (schematic designator R21)
R21_U2 "0R" WP_JS2L 235.864,31.547 r180 top (schematic designator R21)
R22_U1 "10K" WP_0805R 14.173,95.047 r0 top (schematic designator R22)
R22_U2 "10K" WP_0805R 235.763,20.32 r270 top (schematic designator R22)
R23_U1 "2R" WP_0805R 71.018,44.298 r0 top (schematic designator R23)
R23_U2 "2R" WP_0805R 231.394,41.681 r180 top (schematic designator R23)
R24_U1 "100K" WP_0805R 7.62,95.072 r180 top (schematic designator R24)
R24_U2 "100K" WP_0805R 246.507,18.136 r0 top (schematic designator R24)
R25_U1 "36K" WP_0805R 23.317,96.114 r90 top (schematic designator R25)
R25_U2 "36K" WP_0805R 229.54,13.183 r90 top (schematic designator R25)
R26_U1 "2R" WP_0805R 71.018,41.605 r0 top (schematic designator R26)
R26_U2 "2R" WP_0805R 231.445,43.942 r180 top (schematic designator R26)
R27_U1 "2R" WP_0805R 77.064,41.58 r0 top (schematic designator R27)
R27_U2 "2R" WP_0805R 226.339,44.653 r180 top (schematic designator R27)
R28_U1 "10K" WP_0805R 111.074,129.134 r0 top (schematic designator R28)
R28_U2 "10K" WP_0805R 157.785,132.537 r0 top (schematic designator R28)
R29_U1 "5K1" WP_0805R 115.926,129.159 r270 top (schematic designator R29)
R29_U2 "5K1" WP_0805R 154.28,126.949 r90 top (schematic designator R29)
R30_U1 "10K" WP_0805R 91.034,46.152 r270 top (schematic designator R30)
R30_U2 "10K" WP_0805R 213.792,40.589 r90 top (schematic designator R30)
R31_U1 "3K" WP_0805R 54.28,34.976 r180 top (schematic designator R31)
R31_U2 "3K" WP_0805R 248.234,50.952 r0 top (schematic designator R31)
R32_U1 "2R" WP_0805R 71.399,33.122 r0 top (schematic designator R32)
R32_U2 "2R" WP_0805R 230.988,52.807 r180 top (schematic designator R32)
R33_U1 "3K" WP_0805R 54.305,32.664 r180 top (schematic designator R33)
R33_U2 "3K" WP_0805R 248.234,53.315 r0 top (schematic designator R33)
R34_U1 "10K" WP_0805R 154.813,8.306 r270 top (schematic designator R34)
R34_U2 "10K" WP_0805R 152.679,34.214 r180 top (schematic designator R34)
R35_U1 "2R" WP_0805R 71.425,30.48 r0 top (schematic designator R35)
R35_U2 "2R" WP_0805R 231.064,55.194 r180 top (schematic designator R35)
R36_U1 "2R" WP_0805R 76.606,30.353 r0 top (schematic designator R36)
R36_U2 "2R" WP_0805R 226.365,55.626 r180 top (schematic designator R36)
R37_U1 "10K" WP_0805R 81.077,27.991 r90 top (schematic designator R37)
R37_U2 "10K" WP_0805R 221.539,57.963 r270 top (schematic designator R37)
R38_U1 "20K" WP_0805R 154.838,3.429 r270 top (schematic designator R38)
R38_U2 "20K" WP_0805R 147.625,31.953 r180 top (schematic designator R38)
R39_U1 "2R" WP_0805R 71.196,72.593 r0 top (schematic designator R39)
R39_U2 "2R" WP_0805R 231.14,69.875 r180 top (schematic designator R39)
R40_U1 "0K" WP_0805R 31.979,98.958 r0 top (schematic designator R40)
R40_U2 "0K" WP_0805R 225.476,9.855 r180 top (schematic designator R40)
R41_U1 "2R" WP_0805R 71.196,69.596 r0 top (schematic designator R41)
R41_U2 "2R" WP_0805R 231.064,72.441 r180 top (schematic designator R41)
R42_U1 "2R" WP_0805R 75.921,69.621 r0 top (schematic designator R42)
R42_U2 "2R" WP_0805R 226.466,72.542 r180 top (schematic designator R42)
R43_U1 "10K" WP_0805R 80.289,125.044 r0 top (schematic designator R43)
R43_U2 "10K" WP_0805R 174.549,121.183 r90 top (schematic designator R43)
R44_U1 "5K1" WP_0805R 85.369,122.733 r0 top (schematic designator R44)
R44_U2 "5K1" WP_0805R 172.212,123.469 r270 top (schematic designator R44)
R45_U1 "200R" WP_0805R 65.811,119.558 r180 top (schematic designator R45)
R45_U2 "200R" WP_0805R 195.555,123.165 r0 top (schematic designator R45)
R46_U1 "200R" WP_0805R 102.26,123.317 r180 top (schematic designator R46)
R46_U2 "200R" WP_0805R 195.555,120.548 r0 top (schematic designator R46)
R47_U1 "10K" WP_0805R 91.694,72.365 r90 top (schematic designator R47)
R47_U2 "10K" WP_0805R 214.528,70.637 r270 top (schematic designator R47)
R48_U1 "3K" WP_0805R 53.95,62.814 r180 top (schematic designator R48)
R48_U2 "3K" WP_0805R 248.158,80.112 r0 top (schematic designator R48)
R49_U1 "2R" WP_0805R 71.272,61.493 r0 top (schematic designator R49)
R49_U2 "2R" WP_0805R 231.013,80.315 r180 top (schematic designator R49)
R50_U1 "3K" WP_0805R 53.95,60.35 r180 top (schematic designator R50)
R50_U2 "3K" WP_0805R 248.158,82.55 r0 top (schematic designator R50)
R52_U1 "2R" WP_0805R 71.222,58.674 r0 top (schematic designator R52)
R52_U2 "2R" WP_0805R 230.937,83.109 r180 top (schematic designator R52)
R53_U1 "2R" WP_0805R 75.997,58.699 r0 top (schematic designator R53)
R53_U2 "2R" WP_0805R 226.187,83.185 r180 top (schematic designator R53)
R54_U1 "10K" WP_0805R 80.569,56.388 r90 top (schematic designator R54)
R54_U2 "10K" WP_0805R 221.437,85.573 r270 top (schematic designator R54)
R55_U1 "3K" WP_0805R 56.286,119.304 r180 top (schematic designator R55)
R55_U2 "3K" WP_0805R 211.15,120.65 r90 top (schematic designator R55)
R56_U1 "10K" WP_0805R 87.909,118.186 r0 top (schematic designator R56)
R56_U2 "10K" WP_0805R 188.849,120.244 r90 top (schematic designator R56)
R57_U1 "5K1" WP_0805R 92.456,120.548 r0 top (schematic designator R57)
R57_U2 "5K1" WP_0805R 191.16,122.657 r270 top (schematic designator R57)
R58_U1 "3K" WP_0805R 53.924,117.018 r0 top (schematic designator R58)
R58_U2 "3K" WP_0805R 213.69,120.625 r90 top (schematic designator R58)
R59_U1 "2R" WP_0805R 71.069,102.26 r0 top (schematic designator R59)
R59_U2 "2R" WP_0805R 230.962,98.527 r180 top (schematic designator R59)
R60_U1 "2R" WP_0805R 71.069,99.974 r0 top (schematic designator R60)
R60_U2 "2R" WP_0805R 230.962,101.524 r180 top (schematic designator R60)
R61_U1 "2R" WP_0805R 77.546,99.441 r0 top (schematic designator R61)
R61_U2 "2R" WP_0805R 226.517,101.549 r180 top (schematic designator R61)
R62_U1 "10K" WP_0805R 90.17,100.787 r90 top (schematic designator R62)
R62_U2 "10K" WP_0805R 213.944,98.654 r270 top (schematic designator R62)
R63_U1 "3K" WP_0805R 53.772,94.285 r180 top (schematic designator R63)
R63_U2 "3K" WP_0805R 247.929,107.391 r0 top (schematic designator R63)
R64_U1 "2R" WP_0805R 70.891,89.891 r0 top (schematic designator R64)
R64_U2 "2R" WP_0805R 231.038,108.433 r180 top (schematic designator R64)
R65_U1 "3K" WP_0805R 53.772,91.821 r180 top (schematic designator R65)
R65_U2 "3K" WP_0805R 247.955,109.703 r0 top (schematic designator R65)
R66_U1 "2R" WP_0805R 70.917,87.046 r0 top (schematic designator R66)
R66_U2 "2R" WP_0805R 231.064,110.846 r180 top (schematic designator R66)
R67_U1 "2R" WP_0805R 75.54,87.046 r0 top (schematic designator R67)
R67_U2 "2R" WP_0805R 226.365,111.277 r180 top (schematic designator R67)
R68_U1 "10K" WP_0805R 80.315,84.811 r90 top (schematic designator R68)
R68_U2 "10K" WP_0805R 221.615,113.64 r270 top (schematic designator R68)
R69_U1 "10K" WP_0805R 64.287,115.087 r180 top (schematic designator R69)
R69_U2 "10K" WP_0805R 143.789,131.877 r180 top (schematic designator R69)
R70_U1 "5K1" WP_0805R 61.9,112.801 r0 top (schematic designator R70)
R70_U2 "5K1" WP_0805R 141.326,125.374 r270 top (schematic designator R70)
R71_U1 "3K" WP_0805R 102.26,118.11 r90 top (schematic designator R71)
R71_U2 "3K" WP_0805R 152.298,106.553 r270 top (schematic designator R71)
R72_U1 "20K" WP_0805R 70.917,111.887 r180 top (schematic designator R72)
R72_U2 "20K" WP_0805R 143.916,117.831 r90 top (schematic designator R72)
R73_U1 "10K" WP_0805R 84.353,109.779 r180 top (schematic designator R73)
R73_U2 "10K" WP_0805R 143.84,113.386 r90 top (schematic designator R73)
R74_U1 "10K/1%" WP_0805R 112.522,112.217 r270 top (schematic designator R74)
R74_U2 "10K/1%" WP_0805R 147.269,89.052 r0 top (schematic designator R74)
R75_U1 "10K/1%" WP_0805R 110.185,112.217 r270 top (schematic designator R75)
R75_U2 "10K/1%" WP_0805R 147.32,91.44 r0 top (schematic designator R75)
R76_U1 "1K/1%" WP_0805R 107.848,109.83 r90 top (schematic designator R76)
R76_U2 "1K/1%" WP_0805R 149.555,93.599 r90 top (schematic designator R76)
R77_U1 "20K" WP_0805R 77.775,112.395 r90 top (schematic designator R77)
R77_U2 "20K" WP_0805R 146.863,117.729 r90 top (schematic designator R77)
R78_U1 "10K" WP_0805R 84.328,112.42 r180 top (schematic designator R78)
R78_U2 "10K" WP_0805R 146.888,113.259 r90 top (schematic designator R78)
R79 "0R" WP_JS2L 135.941,15.138 r180 top
R80 "0R" WP_JS2L 165.532,40.843 r90 top
U1_U1 "MCP604T-I/SL" WP_SOIC14 122.403,119.939 r0 top (schematic designator U1)
U1_U2 "MCP604T-I/SL" WP_SOIC14 158.267,120.523 r0 top (schematic designator U1)
U2_U1 "AS1117-2V5" WP_SOT223 135.255,120.218 r270 top (schematic designator U2)
U2_U2 "AS1117-2V5" WP_SOT223 170.993,120.548 r270 top (schematic designator U2)
U3_U1 "TPS54531DDAR" WP_SOIC8P 10.185,101.752 r0 top (schematic designator U3)
U3_U2 "TPS54531DDAR" WP_SOIC8P 243.764,12.141 r180 top (schematic designator U3)
U4_U1 "OPA2188AIDR" WP_SOIC8 103.759,130.023 r0 top (schematic designator U4)
U4_U2 "OPA2188AIDR" WP_SOIC8 161.468,126.086 r180 top (schematic designator U4)
U5_U1 "ACS712ELCTR-05B-T" WP_SOIC8 110.795,4.242 r180 top (schematic designator U5)
U5_U2 "ACS712ELCTR-05B-T" WP_SOIC8 153.467,87.782 r90 top (schematic designator U5)
U6_U1 "IR2213S" WP_SOIC16L 68.402,31.166 r180 top (schematic designator U6)
U6_U2 "IR2213S" WP_SOIC16L 233.705,54.254 r0 top (schematic designator U6)
U7_U1 "ACS712ELCTR-05B-T" WP_SOIC8 109.83,33.503 r0 top (schematic designator U7)
U7_U2 "ACS712ELCTR-05B-T" WP_SOIC8 194.894,54.051 r180 top (schematic designator U7)
U8_U1 "OPA2188AIDR" WP_SOIC8 79.858,121.361 r0 top (schematic designator U8)
U8_U2 "OPA2188AIDR" WP_SOIC8 179.299,124.714 r0 top (schematic designator U8)
U9_U1 "IR2213S" WP_SOIC16L 68.301,58.979 r180 top (schematic designator U9)
U9_U2 "IR2213S" WP_SOIC16L 233.782,82.753 r0 top (schematic designator U9)
U10_U1 "ACS712ELCTR-05B-T" WP_SOIC8 109.525,62.408 r0 top (schematic designator U10)
U10_U2 "ACS712ELCTR-05B-T" WP_SOIC8 194.869,81.026 r180 top (schematic designator U10)
U11_U1 "IR2213S" WP_SOIC16L 68.199,89.941 r180 top (schematic designator U11)
U11_U2 "IR2213S" WP_SOIC16L 233.782,111.252 r0 top (schematic designator U11)
U12_U1 "ACS712ELCTR-05B-T" WP_SOIC8 109.347,90.83 r0 top (schematic designator U12)
U12_U2 "ACS712ELCTR-05B-T" WP_SOIC8 194.793,108.56 r180 top (schematic designator U12)
U13_U1 "OPA2188AIDR" WP_SOIC8 67.843,118.466 r0 top (schematic designator U13)
U13_U2 "OPA2188AIDR" WP_SOIC8 148.057,128.067 r270 top (schematic designator U13)
U14_U1 "ACPL-C87B-500E" WP_SOIC8L 99.949,109.372 r180 top (schematic designator U14)
U14_U2 "ACPL-C87B-500E" WP_SOIC8L 144.831,98.908 r90 top (schematic designator U14)
U15_U1 "TLP127" WP_SOP4 64.694,122.301 r180 top (schematic designator U15)
U15_U2 "TLP127" WP_SOP4 200.076,123.165 r0 top (schematic designator U15)
V1_U1 "BAV99" WP_SOT23B 103.886,112.116 r180 top (schematic designator V1)
V1_U2 "BAV99" WP_SOT23B 144.78,95.529 r180 top (schematic designator V1)

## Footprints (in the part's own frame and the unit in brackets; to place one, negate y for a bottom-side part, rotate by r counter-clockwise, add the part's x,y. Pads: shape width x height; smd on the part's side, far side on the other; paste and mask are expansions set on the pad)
JY_TO263-7 [mm]
  rect 0.8x4.5 smd: 1(0,0) 2(1.27,0) 3(2.54,0) 5(5.08,0) 6(6.35,0) 7(7.62,0)
  rect 10.5x11 smd: 4(3.81,10.058)
  silkscreen extent -1.83,-3.17 9.45,15.9
WP_0805_LED [mil]
  rect 50x50 smd: 1(0,0) 2(91,0)
  silkscreen extent -33,-37 138,36
WP_0805C [mil]
  rect 39.37x50 smd: 1(1,-1) 2(95,-1)
  silkscreen extent -30,-38 125,35
WP_0805R [mm]
  rect 1x1.27 smd: 1(0,0) 2(2.388,0)
  silkscreen extent -0.79,-0.94 3.17,0.91
WP_1206CC [mil]
  rect 52.13x60 smd: 1(0,0) 2(135,0)
  silkscreen extent -36,-43 171,42
WP_1210CC [mil]
  rect 60x100 smd: 1(0,0) 2(135,0)
  silkscreen extent -44,-63 179,63
WP_1812D [mil]
  rect 60x125 smd: 1(0,0) 2(185,0)
  silkscreen extent -46,-85 232,85
WP_2420 [mil]
  rect 120x196.85 smd: 1(0,0) 2(248,0)
  silkscreen extent -72,-109 319,108
WP_CRM222-020 [mil]
  oval 40x60 hole 30: 1(0,0) 2(-75,0) 3(-150,0) 4(-225,0) 5(-300,0) 6(-375,0) 7(-450,0) 8(-525,0) 9(-600,0) 10(-675,0) 11(-37.5,75) 12(-112.5,75) 13(-187.5,75) 14(-262.5,75) 15(-337.5,75) 16(-412.5,75) 17(-487.5,75) 18(-562.5,75) 19(-637.5,75) 20(-712.5,75)
  round 106.3 hole 106.3: ""(-1027.51,37.5) ""(315.01,37.5)
  silkscreen extent -1112,-62 400,138
WP_CRM222-030 [mil]
  oval 40x60 hole 30: 1(0,0) 2(-75,0) 3(-150,0) 4(-225,0) 5(-300,0) 6(-375,0) 7(-450,0) 8(-525,0) 9(-600,0) 10(-675,0) 11(-750,0) 12(-825,0) 13(-900,0) 14(-975,0) 15(-1050,0) 16(-37.48,75) 17(-112.48,75) 18(-187.48,75) 19(-262.48,75) 20(-337.48,75) 21(-412.48,75) 22(-487.48,75) 23(-562.48,75) 24(-637.48,75) 25(-712.48,75) 26(-787.48,75) 27(-862.48,75) 28(-937.48,75) 29(-1012.48,75) 30(-1087.48,75)
  round 106.3 hole 106.3: ""(-1402.48,37.5) ""(314.04,37.5)
  silkscreen extent -1489,-63 401,138
WP_JS2L [mm]
  rect 3x5 smd: 1(-0.102,-0.025) 2(3.581,-0.025)
  silkscreen extent -1.78,-2.69 5.26,2.64
WP_LBS6*6 [mm]
  rect 2x3.5 smd: 1(0,0) 2(5.5,0)
  silkscreen extent -1.19,-3 6.71,3
WP_LSIP2 [mil]
  rect 100x100 hole 60: 1(0,0)
  round 100 hole 60: 2(150,0)
  silkscreen extent -106,-136 252,142
WP_SIP2 [mil]
  rect 70x70 hole 40: 1(0,0)
  round 70 hole 40: 2(100,0)
  silkscreen extent -50,-120 160,100
WP_SMA_DO214AC [mm]
  rect 2.35x1.55 smd: 1(0,0) 2(4.3,0)
  silkscreen extent -0.65,-1.5 5.73,1.5, body extent -0.45,-1.3 4.75,1.3, height 2.64
WP_SOD-323 [mm]
  rect 0.9x0.5 smd: 1(-0.025,0.025) 2(2.575,0.025)
  silkscreen extent 0.37,-0.65 2.76,0.7, body extent -0.08,-0.6 2.62,0.65, height 1.1
WP_SOIC8 [mm]
  oval 1.5x0.5 smd: 1(-1.473,-0.66) 2(-1.473,-1.93) 3(-1.473,-3.2) 4(-1.473,-4.47) 5(4.674,-4.47) 6(4.674,-3.2) 7(4.674,-1.93) 8(4.674,-0.66)
  silkscreen extent -0.03,-5.08 3.23,0.03
WP_SOIC8L [mm]
  oval 2x0.6 smd: 1(0,0) 2(0,-1.27) 3(0,-2.54) 4(0,-3.81) 5(11.506,-3.81) 6(11.506,-2.54) 7(11.506,-1.27) 8(11.506,0)
  silkscreen extent 1.45,-4.42 10.06,0.69
WP_SOIC8P [mil]
  oval 59.06x19.68 smd: 1(-2,1) 2(-2,-49) 3(-2,-99) 4(-2,-149) 5(240,-149) 6(240,-99) 7(240,-49) 8(240,1)
  rect 100x120 smd: 9(119,-73)
  silkscreen extent 55,-173 183,28
WP_SOIC14 [mm]
  oval 1.5x0.5 smd: 1(-1.219,-0.889) 2(-1.219,-2.159) 3(-1.219,-3.429) 4(-1.219,-4.699) 5(-1.219,-5.969) 6(-1.219,-7.239) 7(-1.219,-8.509) 8(4.953,-8.484) 9(4.928,-7.214) 10(4.928,-5.994) 11(4.928,-4.674) 12(4.928,-3.404) 13(4.928,-2.159) 14(4.928,-0.864)
  silkscreen extent 0.03,-9.12 3.68,0.05
WP_SOIC16L [mm]
  rect 2x0.4 smd: 1(0,0)
  oval 2x0.4 smd: 2(0,-1.27) 3(0,-2.54) 4(0,-3.81) 5(0,-5.08) 6(0,-6.35) 7(0,-7.62) 8(0,-8.89) 9(10.65,-8.89) 10(10.65,-7.62) 11(10.65,-6.35) 12(10.65,-5.08) 13(10.65,-3.81) 14(10.65,-2.54) 15(10.65,-1.27) 16(10.65,0)
  silkscreen extent 1.84,-9.53 8.81,0.64
WP_SOP4 [mil]
  rect 80x30 smd: 1(11,1)
  oval 80x30 smd: 3(11,-99) 4(293,-99) 6(293,1)
  silkscreen extent 63,-140 241,51
WP_SOT23B [mil]
  rect 30x40 smd: 1(0,0) 2(74,0) 3(37,76)
  silkscreen extent -19,-24 93,100
WP_SOT223 [mm]
  rect 1x1.8 smd: 1(0.864,-4.47) 2(3.175,-4.47) 3(5.436,-4.496)
  rect 4x2.4 smd: 4(3.15,1.473)
  silkscreen extent 0,-3.35 6.27,0
WP_TO263-3 [mil]
  rect 60x150 smd: 1(0,0) 3(200,0)
  rect 400x400 smd: 2(101,403)
  silkscreen extent -134,144 338,617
